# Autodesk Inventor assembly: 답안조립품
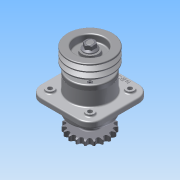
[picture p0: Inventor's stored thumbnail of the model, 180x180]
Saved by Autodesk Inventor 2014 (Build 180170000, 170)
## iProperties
Created: 2015-09
Part Number: 답안조립품
Document SubType Name: Assembly
Designer: study
Author: study
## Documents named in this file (12)
- C:\Users\study\Desktop\450909V1002\답안조립품.iam
- C:\Users\study\Desktop\450909V1002\1-본체.ipt
- C:\Users\study\Desktop\450909V1002\2-커버.ipt
- C:\Users\study\Desktop\450909V1002\3-축.ipt
- C:\Users\study\Desktop\450909V1002\4-V벨트풀리.ipt
- C:\Users\study\Desktop\450909V1002\5-체인 스프로킷.ipt
- C:\Users\study\Desktop\450909V1002\6-베어링 6206.ipt
- C:\Users\study\Desktop\450909V1002\7-부시.ipt
- C:\Users\study\Desktop\450909V1002\8-오일실 30x42.ipt
- C:\Users\study\Desktop\450909V1002\9-M16-너트.ipt
- C:\Users\study\Desktop\450909V1002\10-M6.ipt
- C:\Users\study\Desktop\450909V1002\11-키 6x6.ipt
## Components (23 placed, 11 different names)
1. 1-본체:1
2. 2-커버:1
3. 3-축:1 — 각도:1, 각도:2
4. 4-V벨트풀리:1 — 각도:3
5. 5-체인 스프로킷:1 — 각도:4
6. 6-베어링 6206:1
7. 7-부시:1
8. 8-8-오일실 30x42:1
9. 9-M16 너트:1
10. 11-키 6x6:1 — 각도:1, 각도:3
11. 6-베어링 6206:2
12. 2-커버:2
13. 8-8-오일실 30x42:2
14. 11-키 6x6:2 — 각도:2, 각도:4
15. 9-M16 너트:2
16. 10-M6:2
17. 10-M6:3
18. 10-M6:4
19. 10-M6:5
20. 10-M6:1
21. 10-M6:6
22. 10-M6:7
23. 10-M6:8
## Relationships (4: Angle 4)
- 각도:1 [Angle]: 3-축:1 ↔ 11-키 6x6:1
- 각도:2 [Angle]: 3-축:1 ↔ 11-키 6x6:2
- 각도:3 [Angle]: 4-V벨트풀리:1 ↔ 11-키 6x6:1
- 각도:4 [Angle]: 5-체인 스프로킷:1 ↔ 11-키 6x6:2
## Named parameters: d8_d6 = 0, d9_d7 = 0
